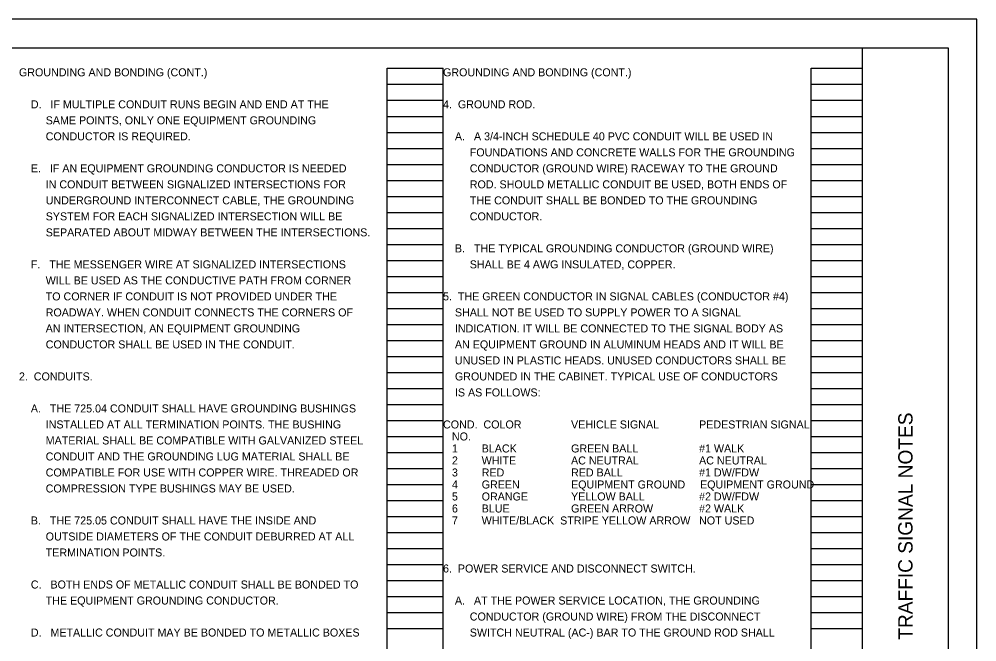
# Model space of a CAD drawing. Extents: x 0 to 34, y 0 to 22.
# Drawn here: x 17.24 to 34, y 11.11 to 22 of the extents above; entities that cross this region are included whole.
import ezdxf

# ---------------------------------------------------------------- set-up
doc = ezdxf.new("R2010")
doc.units = 0
for name, color, linetype in [('SH_Border', 7, 'Continuous'), ('SH_Cut_Line', 7, 'Continuous'), ('SH_Data', 7, 'Continuous'), ('SH_Text', 7, 'Continuous')]:
    doc.layers.add(name, color=color, linetype=linetype)

msp = doc.modelspace()

# ---------------------------------------------------------------- linework, layer by layer
at = {"layer": 'SH_Border'}
msp.add_line((32, 0.5), (32, 21.5), dxfattribs=at)
msp.add_lwpolyline([(1.5, 21.5), (33.5, 21.5), (33.5, 0.5), (1.5, 0.5)], close=True, dxfattribs=at)
at = {"layer": 'SH_Cut_Line'}
msp.add_lwpolyline([(0, 0), (34, 0), (34, 22), (0, 22)], close=True, dxfattribs=at)
at = {"layer": 'SH_Data'}
for p, q in [((23.68, 0.98), (23.68, 21.14)), ((23.68, 21.14), (24.66, 21.14)), ((24.66, 0.98), (24.66, 21.14)), ((31.1, 0.98), (31.1, 21.14)), ((31.1, 21.14), (32, 21.14)), ((32, 0.98), (32, 21.14)), ((23.68, 20.86), (24.66, 20.86)), ((31.1, 20.86), (32, 20.86)), ((23.68, 20.58), (24.66, 20.58)), ((31.1, 20.58), (32, 20.58)), ((23.68, 20.3), (24.66, 20.3)), ((31.1, 20.3), (32, 20.3)), ((23.68, 20.02), (24.66, 20.02)), ((31.1, 20.02), (32, 20.02)), ((23.68, 19.74), (24.66, 19.74)), ((31.1, 19.74), (32, 19.74)), ((23.68, 19.46), (24.66, 19.46)), ((31.1, 19.46), (32, 19.46)), ((23.68, 19.18), (24.66, 19.18)), ((31.1, 19.18), (32, 19.18)), ((23.68, 18.9), (24.66, 18.9)), ((31.1, 18.9), (32, 18.9)), ((23.68, 18.62), (24.66, 18.62)), ((31.1, 18.62), (32, 18.62)), ((23.68, 18.34), (24.66, 18.34)), ((31.1, 18.34), (32, 18.34)), ((23.68, 18.06), (24.66, 18.06)), ((31.1, 18.06), (32, 18.06)), ((23.68, 17.78), (24.66, 17.78)), ((31.1, 17.78), (32, 17.78)), ((23.68, 17.5), (24.66, 17.5)), ((31.1, 17.5), (32, 17.5)), ((23.68, 17.22), (24.66, 17.22)), ((31.1, 17.22), (32, 17.22)), ((23.68, 16.94), (24.66, 16.94)), ((31.1, 16.94), (32, 16.94)), ((23.68, 16.66), (24.66, 16.66)), ((31.1, 16.66), (32, 16.66)), ((23.68, 16.38), (24.66, 16.38)), ((31.1, 16.38), (32, 16.38)), ((23.68, 16.1), (24.66, 16.1)), ((31.1, 16.1), (32, 16.1)), ((23.68, 15.82), (24.66, 15.82)), ((31.1, 15.82), (32, 15.82)), ((23.68, 15.54), (24.66, 15.54)), ((31.1, 15.54), (32, 15.54)), ((23.68, 15.26), (24.66, 15.26)), ((31.1, 15.26), (32, 15.26)), ((23.68, 14.98), (24.66, 14.98)), ((31.1, 14.98), (32, 14.98)), ((23.68, 14.7), (24.66, 14.7)), ((31.1, 14.7), (32, 14.7)), ((23.68, 14.42), (24.66, 14.42)), ((31.1, 14.42), (32, 14.42)), ((23.68, 14.14), (24.66, 14.14)), ((31.1, 14.14), (32, 14.14)), ((23.68, 13.86), (24.66, 13.86)), ((31.1, 13.86), (32, 13.86)), ((23.68, 13.58), (24.66, 13.58)), ((31.1, 13.58), (32, 13.58)), ((23.68, 13.3), (24.66, 13.3)), ((31.1, 13.3), (32, 13.3)), ((23.68, 13.02), (24.66, 13.02)), ((31.1, 13.02), (32, 13.02)), ((23.68, 12.74), (24.66, 12.74)), ((31.1, 12.74), (32, 12.74)), ((23.68, 12.46), (24.66, 12.46)), ((31.1, 12.46), (32, 12.46)), ((23.68, 12.18), (24.66, 12.18)), ((31.1, 12.18), (32, 12.18)), ((23.68, 11.9), (24.66, 11.9)), ((31.1, 11.9), (32, 11.9)), ((23.68, 11.62), (24.66, 11.62)), ((31.1, 11.62), (32, 11.62)), ((23.68, 11.34), (24.66, 11.34)), ((31.1, 11.34), (32, 11.34))]:
    msp.add_line(p, q, dxfattribs=at)

# ---------------------------------------------------------------- texts
msp.add_text('TRAFFIC SIGNAL NOTES', height=0.25, rotation=90, dxfattribs=at).set_placement((32.875, 11.144))
at = {"layer": 'SH_Text'}
for s, p in [('GROUNDING AND BONDING (CONT.)', (17.24, 21)), ('GROUNDING AND BONDING (CONT.)', (24.66, 21)), ('    D.   IF MULTIPLE CONDUIT RUNS BEGIN AND END AT THE', (17.24, 20.44)), ('4.  GROUND ROD.', (24.66, 20.44)), ('         SAME POINTS, ONLY ONE EQUIPMENT GROUNDING', (17.24, 20.16)), ('         CONDUCTOR IS REQUIRED.', (17.24, 19.88)), ('    A.   A 3/4-INCH SCHEDULE 40 PVC CONDUIT WILL BE USED IN', (24.66, 19.88)), ('         FOUNDATIONS AND CONCRETE WALLS FOR THE GROUNDING', (24.66, 19.6)), ('    E.   IF AN EQUIPMENT GROUNDING CONDUCTOR IS NEEDED', (17.24, 19.32)), ('         CONDUCTOR (GROUND WIRE) RACEWAY TO THE GROUND', (24.66, 19.32)), ('         IN CONDUIT BETWEEN SIGNALIZED INTERSECTIONS FOR', (17.24, 19.04)), ('         ROD. SHOULD METALLIC CONDUIT BE USED, BOTH ENDS OF', (24.66, 19.04)), ('         UNDERGROUND INTERCONNECT CABLE, THE GROUNDING', (17.24, 18.76)), ('         THE CONDUIT SHALL BE BONDED TO THE GROUNDING', (24.66, 18.76)), ('         SYSTEM FOR EACH SIGNALIZED INTERSECTION WILL BE', (17.24, 18.48)), ('         CONDUCTOR.', (24.66, 18.48)), ('         SEPARATED ABOUT MIDWAY BETWEEN THE INTERSECTIONS.', (17.24, 18.2)), ('    B.   THE TYPICAL GROUNDING CONDUCTOR (GROUND WIRE)', (24.66, 17.92)), ('    F.   THE MESSENGER WIRE AT SIGNALIZED INTERSECTIONS', (17.24, 17.64)), ('         SHALL BE 4 AWG INSULATED, COPPER.', (24.66, 17.64)), ('         WILL BE USED AS THE CONDUCTIVE PATH FROM CORNER', (17.24, 17.36)), ('         TO CORNER IF CONDUIT IS NOT PROVIDED UNDER THE', (17.24, 17.08)), ('5.  THE GREEN CONDUCTOR IN SIGNAL CABLES (CONDUCTOR #4)', (24.66, 17.08)), ('         ROADWAY. WHEN CONDUIT CONNECTS THE CORNERS OF', (17.24, 16.8)), ('    SHALL NOT BE USED TO SUPPLY POWER TO A SIGNAL', (24.66, 16.8)), ('         AN INTERSECTION, AN EQUIPMENT GROUNDING', (17.24, 16.52)), ('    INDICATION. IT WILL BE CONNECTED TO THE SIGNAL BODY AS', (24.66, 16.52)), ('         CONDUCTOR SHALL BE USED IN THE CONDUIT.', (17.24, 16.24)), ('    AN EQUIPMENT GROUND IN ALUMINUM HEADS AND IT WILL BE', (24.66, 16.24)), ('    UNUSED IN PLASTIC HEADS. UNUSED CONDUCTORS SHALL BE', (24.66, 15.96)), ('2.  CONDUITS.', (17.24, 15.68)), ('    GROUNDED IN THE CABINET. TYPICAL USE OF CONDUCTORS', (24.66, 15.68)), ('    IS AS FOLLOWS:', (24.66, 15.4)), ('    A.   THE 725.04 CONDUIT SHALL HAVE GROUNDING BUSHINGS', (17.24, 15.12)), ('         INSTALLED AT ALL TERMINATION POINTS. THE BUSHING', (17.24, 14.84)), ('COND.  COLOR', (24.66, 14.84)), ('VEHICLE SIGNAL       ', (26.9, 14.84)), ('PEDESTRIAN SIGNAL', (29.14, 14.84)), ('   NO.', (24.66, 14.63)), ('         MATERIAL SHALL BE COMPATIBLE WITH GALVANIZED STEEL', (17.24, 14.56)), ('         CONDUIT AND THE GROUNDING LUG MATERIAL SHALL BE', (17.24, 14.28)), ('   1        BLACK        ', (24.66, 14.42)), ('GREEN BALL           ', (26.9, 14.42)), ('#1 WALK', (29.14, 14.42)), ('   2        WHITE       ', (24.66, 14.21)), ('AC NEUTRAL           ', (26.9, 14.21)), ('AC NEUTRAL', (29.14, 14.21)), ('         COMPATIBLE FOR USE WITH COPPER WIRE. THREADED OR', (17.24, 14)), ('   3        RED          ', (24.66, 14)), ('RED BALL             ', (26.9, 14)), ('#1 DW/FDW', (29.14, 14)), ('   4        GREEN        ', (24.66, 13.79)), ('EQUIPMENT GROUND     EQUIPMENT GROUND', (26.9, 13.79)), ('         COMPRESSION TYPE BUSHINGS MAY BE USED.', (17.24, 13.72)), ('   5        ORANGE    ', (24.66, 13.58)), ('YELLOW BALL          ', (26.9, 13.58)), ('#2 DW/FDW', (29.14, 13.58)), ('   6        BLUE         ', (24.66, 13.37)), ('GREEN ARROW          ', (26.9, 13.37)), ('#2 WALK', (29.14, 13.37)), ('    B.   THE 725.05 CONDUIT SHALL HAVE THE INSIDE AND', (17.24, 13.16)), ('   7        WHITE/BLACK  STRIPE YELLOW ARROW  ', (24.66, 13.16)), ('NOT USED', (29.14, 13.16)), ('         OUTSIDE DIAMETERS OF THE CONDUIT DEBURRED AT ALL', (17.24, 12.88)), ('         TERMINATION POINTS.', (17.24, 12.6)), ('6.  POWER SERVICE AND DISCONNECT SWITCH.', (24.66, 12.32)), ('    C.   BOTH ENDS OF METALLIC CONDUIT SHALL BE BONDED TO', (17.24, 12.04)), ('         THE EQUIPMENT GROUNDING CONDUCTOR.', (17.24, 11.76)), ('    A.   AT THE POWER SERVICE LOCATION, THE GROUNDING', (24.66, 11.76)), ('         CONDUCTOR (GROUND WIRE) FROM THE DISCONNECT', (24.66, 11.48)), ('    D.   METALLIC CONDUIT MAY BE BONDED TO METALLIC BOXES', (17.24, 11.2)), ('         SWITCH NEUTRAL (AC-) BAR TO THE GROUND ROD SHALL', (24.66, 11.2))]:
    msp.add_text(s, height=0.14, dxfattribs=at).set_placement(p)

doc.saveas('drawing.dxf')
